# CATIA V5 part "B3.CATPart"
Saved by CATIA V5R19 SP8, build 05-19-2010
Part number: B3
Publications: "Li", "La", "e", "r"
Bounding box of the stored display mesh (mm): x -15 to 165, y -25 to 25, z -14.942 to 14.942
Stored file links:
  C:\Users\ThinkMotion\Desktop\EU_thinkMotion\iao\IAO_MMS_Groupe3\evulliez\evulliez\evulliez\Mecanisme\B3.CATPart
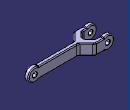
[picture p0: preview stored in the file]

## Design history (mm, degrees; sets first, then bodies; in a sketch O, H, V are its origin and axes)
Parameters
  Li = 150 mm
  La = 25 mm
  e = 10 mm
  r = 5 mm
Body1 (main body)
  Point1: (0, 0, 0)
  Line1: type PtDir, RefPoint Point1, Direction (1, 0, 0), Start 0, End 150 {= Li}
  Line2: type PtDir, RefPoint Point1, Direction (0, 1, 0), Start -25, End 25 {= (5*e )/2}
  Line3: type PtDir, RefPoint vertex of Line1, Direction (0, 1, 0), Start -5, End 5 {= e /2}
  Sketch1 on zx-plane, origin (0, 0, 0), H (-1, 0, 0), V (0, 0, 1)
    line L1 (-141.7084, 12.5) -> (-8.2916, 12.5)
    point P1 (-141.7084, 12.5)
    point P2 (-8.2916, 12.5)
    line L2 (-141.7084, -12.5) -> (-8.2916, -12.5)
    point P3 (-141.7084, -12.5)
    point P4 (-8.2916, -12.5)
    reference projected line E1 (-30, 0) -> (-165, 0) from Sketch2.L9
    arc A1 centre (-150, 0) radius 15 from (-141.7084, 12.5) to (-141.7084, -12.5) ccw
    point P5 (-150, 0)
    point P6 (-141.7084, 12.5)
    point P7 (-141.7084, -12.5)
    reference projected point E2 (-150, 0) from vertex of Line1
    reference projected point E3 (-165, 0) from vertex [element of Sketch2 | element of Sketch2]
    arc A2 centre (0, 0) radius 15 from (-8.2916, -12.5) to (-8.2916, 12.5) ccw
    point P8 (0, 0)
    point P9 (-8.2916, -12.5)
    point P10 (-8.2916, 12.5)
    reference projected point E4 (0, 0) from Point1
    reference projected point E5 (15, 0) from vertex [element of Sketch2 | element of Sketch2]
    distance E1 L1 = 12.5 {= La /2}
    distance L2 L1 = 25 {= La}
    horizontal: L1 H, L2 H
    coincidence: P5 E2, P6 P1, P3 P7, A1 E3, P8 E4, E5 A2, P2 P10, P9 P4
  Sketch2 on xy-plane, origin (0, 0, 0), H (1, 0, 0), V (0, 1, 0)
    line L1 (-15, -25) -> (30, -25)
    point P2 (30, -25)
    line L2 (-15, -25) -> (-15, -15)
    line L3 (-15, -15) -> (20, -15)
    point P4 (20, -15)
    point P5 (20, 15)
    line L4 (20, 15) -> (-15, 15)
    point P6 (-15, 15)
    line L5 (-15, 15) -> (-15, 25)
    line L6 (-15, 25) -> (30, 25)
    point P8 (30, 25)
    point P9 (50, 5)
    line L7 (50, 5) -> (165, 5)
    line L8 (165, 5) -> (165, -5)
    line L9 (165, -5) -> (50, -5)
    point P12 (50, -5)
    reference projected point E1 (150, 5) from vertex of Line3
    reference projected point E2 (150, -5) from vertex of Line3
    reference projected line E3 (150, -5) -> (150, 5) from Line3
    reference projected line E4 (0, -15) -> (0, 15) from Line2
    reference projected point E5 (0, -25) from vertex of Line2
    reference projected point E6 (0, 25) from vertex of Line2
    reference projected line E7 (0, -25) -> (0, 25) from Line2
    reference projected line E8 (0, -25) -> (0, 25) from Line2
    line L10 (20, 15) -> (30, 5)
    point P13 (30, 5)
    reference projected line E9 (0, -25) -> (0, 25) from Line2
    reference projected line E10 (0, -25) -> (0, 25) from Line2
    reference projected line E11 (0, -25) -> (0, 25) from Line2
    reference projected line E12 (0, -25) -> (0, 25) from Line2
    reference projected line E13 (0, -25) -> (0, 25) from Line2
    line L11 (50, -5) -> (30, -25)
    line L12 (30, 25) -> (50, 5)
    line L13 (20, -15) -> (30, -5)
    point P14 (30, -5)
    reference projected line E14 (0, -25) -> (0, 25) from Line2
    arc A1 centre (25, 0) radius 7.0711 from (30, -5) to (30, 5) ccw
    point P16 (30, -5)
    point P17 (30, 5)
    length L2 = 10 {= e}
    length L5 = 10 {= e}
    distance E3 L8 = 15 {= r +10mm}
    distance E4 L5 = 15 {= r +10mm}
    distance E7 P5 = 20 {= r +15mm}
    distance E8 P4 = 20 {= r +15mm}
    distance E9 P13 = 30 {= r +15mm+e}
    distance E10 P8 = 30 {= r +15mm+e}
    distance E11 P2 = 30 {= r +15mm+e}
    distance E12 P9 = 50 {= r +25mm+2*e}
    distance E13 P12 = 50 {= r +25mm+2*e}
    distance E14 P14 = 30 {= r +e +15mm}
    horizontal: L1 H, L3 H, L4 H, L6 H, L7 H, L9 H
    vertical: L2 V, L5 V, L8 V
    coincidence: P6 L2, E1 L7, E2 L9, E5 L1, E6 L6, P17 P13, P16 P14
    parallelism: L13 L11, L10 L12
    tangency: A1 L10
  SolidCombine1: FirstComponentProfile Sketch1, FirstComponentDirection Sketch1, SecondComponentProfile Sketch2, SecondComponentDirection Sketch2
  Sketch3 on face of SolidCombine1 from Sketch2.L6, origin (0, 25, 0), H (1, 0, 0), V (0, 0, -1)
    point P1 (0, 0)
    reference projected point E1 (0, 0) from vertex of Line2
    coincidence: E1 P1
  Hole1: placed by Sketch3, at (0, 25, 0) direction (0, -1, 0), diameter 10 {= r *2}, through (limit type 3)
  Sketch4 on face of SolidCombine1 from Sketch2.L7, origin (150, 5, 0), H (1, 0, 0), V (0, 0, -1)
    point P1 (0, 0)
    reference projected point E1 (0, 0) from vertex of Line3
    coincidence: E1 P1
  Hole2: placed by Sketch4, at (150, 5, 0) direction (0, -1, 0), diameter 10 {= r *2}, through (limit type 3)
  Fillet1: radius 1, on edge [face of Hole1 | face of SolidCombine1 from Sketch2.L3]; edge [face of Hole1 | face of SolidCombine1 from Sketch2.L6]; edge [face of Hole2 | face of SolidCombine1 from Sketch2.L7]; edge [face of Hole1 | face of SolidCombine1 from Sketch2.L4]; edge [face of SolidCombine1 from Sketch2.L1 | face of Hole1]; edge [face of Hole2 | face of SolidCombine1 from Sketch2.L9]
  Fillet2: radius 2, on edge [face of SolidCombine1 from Sketch2.L3 | face of SolidCombine1 from Sketch1.A2]; edge [face of SolidCombine1 from Sketch1.A2 | face of SolidCombine1 from Sketch2.L1]; edge [face of SolidCombine1 from Sketch2.L4 | face of SolidCombine1 from Sketch1.A2]; edge [face of SolidCombine1 from Sketch2.L6 | face of SolidCombine1 from Sketch1.A2]; edge [face of SolidCombine1 from Sketch2.L4 | face of SolidCombine1 from Sketch1.L1]; edge [face of SolidCombine1 from Sketch2.L10 | face of SolidCombine1 from Sketch1.L1]; edge [face of SolidCombine1 from Sketch1.L1 | face of SolidCombine1 from Sketch2.L13]; edge [face of SolidCombine1 from Sketch1.L1 | face of SolidCombine1 from Sketch2.L3]; edge [face of SolidCombine1 from Sketch2.L1 | face of SolidCombine1 from Sketch1.L1]; edge [face of SolidCombine1 from Sketch1.L2 | face of SolidCombine1 from Sketch2.L1]; edge [face of SolidCombine1 from Sketch2.L11 | face of SolidCombine1 from Sketch1.L2]; edge [face of SolidCombine1 from Sketch1.L1 | face of SolidCombine1 from Sketch2.L11]; edge [face of SolidCombine1 from Sketch1.L1 | face of SolidCombine1 from Sketch2.L9]; edge [face of SolidCombine1 from Sketch2.L9 | face of SolidCombine1 from Sketch1.L2]; edge [face of SolidCombine1 from Sketch1.L1 | face of SolidCombine1 from Sketch2.L6]; edge [face of SolidCombine1 from Sketch1.L1 | face of SolidCombine1 from Sketch2.L12]; edge [face of SolidCombine1 from Sketch2.L7 | face of SolidCombine1 from Sketch1.L1]; edge [face of SolidCombine1 from Sketch2.L7 | face of SolidCombine1 from Sketch1.A1]; edge [face of SolidCombine1 from Sketch2.L9 | face of SolidCombine1 from Sketch1.A1]; edge [face of SolidCombine1 from Sketch2.L3 | face of SolidCombine1 from Sketch1.L2]; edge [face of SolidCombine1 from Sketch2.L13 | face of SolidCombine1 from Sketch1.L2]; edge [face of SolidCombine1 from Sketch1.L2 | face of SolidCombine1 from Sketch2.L10]; edge [face of SolidCombine1 from Sketch1.L2 | face of SolidCombine1 from Sketch2.L4]; edge [face of SolidCombine1 from Sketch2.L6 | face of SolidCombine1 from Sketch1.L2]; edge [face of SolidCombine1 from Sketch2.L12 | face of SolidCombine1 from Sketch1.L2]; edge [face of SolidCombine1 from Sketch1.L2 | face of SolidCombine1 from Sketch2.L7]
  Fillet3: radius 10, on edge [face of SolidCombine1 from Sketch2.L3 | face of SolidCombine1 from Sketch2.L13]; edge [face of SolidCombine1 from Sketch2.L10 | face of SolidCombine1 from Sketch2.L4]; edge [face of SolidCombine1 from Sketch2.L11 | face of SolidCombine1 from Sketch2.L1]; edge [face of SolidCombine1 from Sketch2.L9 | face of SolidCombine1 from Sketch2.L11]; edge [face of SolidCombine1 from Sketch2.L6 | face of SolidCombine1 from Sketch2.L12]; edge [face of SolidCombine1 from Sketch2.L12 | face of SolidCombine1 from Sketch2.L7]
  Fillet4: radius 5, on edge [face of SolidCombine1 from Sketch1.A2 | face of SolidCombine1 from Sketch1.L2] (x2); edge [face of SolidCombine1 from Sketch1.L2 | face of SolidCombine1 from Sketch1.A1]; edge [face of SolidCombine1 from Sketch1.A1 | face of SolidCombine1 from Sketch1.L1]; edge [face of SolidCombine1 from Sketch1.L1 | face of SolidCombine1 from Sketch1.A2] (x2)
